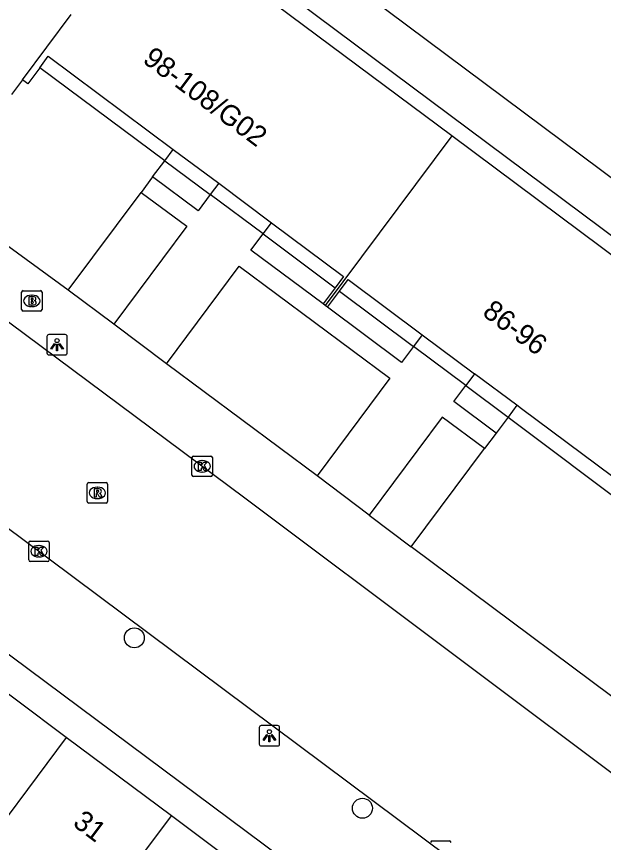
# Model space of a CAD drawing. Extents: x 160026 to 161302, y 384757 to 385701.
# Drawn here: x 160322.72 to 160351.49, y 385268.03 to 385308.52 of the extents above; entities that cross this region are included whole.
import ezdxf

# ---------------------------------------------------------------- set-up
doc = ezdxf.new("R2010")
doc.units = 0
for name, color, linetype in [('IMGEO_Boom', 7, 'Continuous'), ('IMGEO_Brandkraan', 7, 'Continuous'), ('IMGEO_Groenvoorziening', 7, 'Continuous'), ('IMGEO_Kolk', 7, 'Continuous'), ('IMGEO_Lichtpunt', 7, 'Continuous'), ('IMGEO_Pand', 7, 'Continuous'), ('IMGEO_Pand_nummerreeks', 7, 'Continuous'), ('IMGEO_Rijbaan_lokaal_gesloten', 7, 'Continuous'), ('IMGEO_Rioolput', 7, 'Continuous'), ('IMGEO_Voetpad_open', 7, 'Continuous')]:
    doc.layers.add(name, color=color, linetype=linetype)

msp = doc.modelspace()

# ---------------------------------------------------------------- linework, layer by layer
at = {"layer": 'IMGEO_Boom'}
for centre in [(160328.493, 385278.063), (160339.675, 385269.709)]:
    msp.add_circle(centre, 0.489, dxfattribs=at)
at = {"layer": 'IMGEO_Brandkraan'}
for p, q in [((160322.967, 385294.157), (160322.967, 385295.009)), ((160323.042, 385295.083), (160323.894, 385295.083)), ((160323.455, 385294.863), (160323.48, 385294.863)), ((160323.968, 385295.009), (160323.968, 385294.157)), ((160323.894, 385294.083), (160323.042, 385294.083)), ((160323.478, 385294.303), (160323.453, 385294.303))]:
    msp.add_line(p, q, dxfattribs=at)
for points in [[(160322.967, 385294.157), (160322.967, 385295.009)], [(160323.042, 385295.083), (160323.894, 385295.083)], [(160323.968, 385295.009), (160323.968, 385294.157)], [(160323.315, 385294.783), (160323.315, 385294.383), (160323.528, 385294.383)], [(160323.546, 385294.783), (160323.315, 385294.783)], [(160323.494, 385294.702), (160323.44, 385294.702), (160323.44, 385294.626)], [(160323.44, 385294.626), (160323.493, 385294.626)], [(160323.502, 385294.55), (160323.44, 385294.55), (160323.44, 385294.469)], [(160323.44, 385294.469), (160323.502, 385294.469)], [(160323.894, 385294.083), (160323.042, 385294.083)]]:
    msp.add_lwpolyline(points, dxfattribs=at)
for centre, radius, start, end in [((160323.044, 385295.007), 0.0765, 91.552, 178.448), ((160323.044, 385295.007), 0.0765, 91.552, 178.448), ((160323.892, 385295.007), 0.0765, 1.552, 88.448), ((160323.892, 385295.007), 0.0765, 1.552, 88.448), ((160323.495, 385294.664), 0.0379, 267.8285, 90.9355), ((160323.503, 385294.509), 0.0404, 269.8759, 90.5077), ((160323.55, 385294.638), 0.145, 59.4692, 91.5367), ((160323.575, 385294.685), 0.0922, 285.5137, 58.1501), ((160323.58, 385294.493), 0.105, 301.3115, 78.989), ((160323.044, 385294.159), 0.0765, 181.552, 268.448), ((160323.044, 385294.159), 0.0765, 181.552, 268.448), ((160323.534, 385294.634), 0.251, 268.6676, 293.5347), ((160323.892, 385294.159), 0.0765, 271.552, 358.448), ((160323.892, 385294.159), 0.0765, 271.552, 358.448)]:
    msp.add_arc(centre, radius, start, end, dxfattribs=at)
for centre, major_axis, ratio, start_param, end_param in [((160323.454, 385294.583), (-0.387, 0.002), 0.722429, 4.712389, 7.853982), ((160323.479, 385294.583), (-0.39, 0.002), 0.717154, 1.570796, 4.712389)]:
    msp.add_ellipse(centre, major_axis=major_axis, ratio=ratio, start_param=start_param, end_param=end_param, dxfattribs=at)
at = {"layer": 'IMGEO_Groenvoorziening'}
for points in [[(160329.983, 385301.454), (160332.215, 385299.791)], [(160334.805, 385297.862), (160338.342, 385295.227)], [(160338.543, 385295.063), (160342.176, 385292.346)], [(160344.743, 385290.426), (160346.813, 385288.878)]]:
    msp.add_lwpolyline(points, dxfattribs=at)
at = {"layer": 'IMGEO_Kolk'}
for p, q in [((160331.319, 385286.046), (160331.319, 385286.898)), ((160331.394, 385286.972), (160332.246, 385286.972)), ((160331.807, 385286.752), (160331.832, 385286.752)), ((160332.32, 385286.898), (160332.32, 385286.046)), ((160332.246, 385285.972), (160331.394, 385285.972)), ((160331.83, 385286.192), (160331.805, 385286.192)), ((160323.316, 385281.881), (160323.316, 385282.733)), ((160323.391, 385282.807), (160324.243, 385282.807)), ((160324.317, 385282.733), (160324.317, 385281.881)), ((160323.804, 385282.587), (160323.829, 385282.587)), ((160323.827, 385282.027), (160323.802, 385282.027)), ((160324.243, 385281.807), (160323.391, 385281.807)), ((160343.093, 385268.104), (160343.945, 385268.104))]:
    msp.add_line(p, q, dxfattribs=at)
for points in [[(160331.319, 385286.046), (160331.319, 385286.898)], [(160331.394, 385286.972), (160332.246, 385286.972)], [(160332.32, 385286.898), (160332.32, 385286.046)], [(160331.64, 385286.672), (160331.763, 385286.672), (160331.763, 385286.521), (160331.893, 385286.672), (160332.057, 385286.672), (160331.911, 385286.521), (160332.064, 385286.272), (160331.912, 385286.272), (160331.827, 385286.436), (160331.763, 385286.369), (160331.763, 385286.272), (160331.64, 385286.272), (160331.64, 385286.672)], [(160332.246, 385285.972), (160331.394, 385285.972)], [(160323.316, 385281.881), (160323.316, 385282.733)], [(160323.391, 385282.807), (160324.243, 385282.807)], [(160324.317, 385282.733), (160324.317, 385281.881)], [(160323.637, 385282.507), (160323.76, 385282.507), (160323.76, 385282.356), (160323.89, 385282.507), (160324.054, 385282.507), (160323.908, 385282.356), (160324.061, 385282.107), (160323.909, 385282.107), (160323.824, 385282.271), (160323.76, 385282.204), (160323.76, 385282.107), (160323.637, 385282.107), (160323.637, 385282.507)], [(160324.243, 385281.807), (160323.391, 385281.807)], [(160343.093, 385268.104), (160343.945, 385268.104)]]:
    msp.add_lwpolyline(points, dxfattribs=at)
for centre, start, end in [((160331.396, 385286.896), 91.552, 178.448), ((160331.396, 385286.896), 91.552, 178.448), ((160332.244, 385286.896), 1.552, 88.448), ((160332.244, 385286.896), 1.552, 88.448), ((160331.396, 385286.048), 181.552, 268.448), ((160331.396, 385286.048), 181.552, 268.448), ((160332.244, 385286.048), 271.552, 358.448), ((160332.244, 385286.048), 271.552, 358.448), ((160323.393, 385282.731), 91.552, 178.448), ((160323.393, 385282.731), 91.552, 178.448), ((160324.241, 385282.731), 1.552, 88.448), ((160324.241, 385282.731), 1.552, 88.448), ((160323.393, 385281.883), 181.552, 268.448), ((160323.393, 385281.883), 181.552, 268.448), ((160324.241, 385281.883), 271.552, 358.448), ((160324.241, 385281.883), 271.552, 358.448), ((160343.095, 385268.028), 91.552, 178.448), ((160343.095, 385268.028), 91.552, 178.448), ((160343.943, 385268.028), 1.552, 88.448), ((160343.943, 385268.028), 1.552, 88.448)]:
    msp.add_arc(centre, 0.0765, start, end, dxfattribs=at)
for centre, major_axis, ratio, start_param, end_param in [((160331.806, 385286.472), (-0.387, 0.002), 0.722429, 4.712389, 7.853982), ((160331.831, 385286.472), (-0.39, 0.002), 0.717154, 1.570796, 4.712389), ((160323.803, 385282.307), (-0.387, 0.002), 0.722429, 4.712389, 7.853982), ((160323.828, 385282.307), (-0.39, 0.002), 0.717154, 1.570796, 4.712389)]:
    msp.add_ellipse(centre, major_axis=major_axis, ratio=ratio, start_param=start_param, end_param=end_param, dxfattribs=at)
at = {"layer": 'IMGEO_Lichtpunt'}
for p, q in [((160324.205, 385292.837), (160324.205, 385292.03)), ((160324.205, 385292.837), (160324.205, 385292.03)), ((160325.107, 385292.932), (160324.299, 385292.932)), ((160325.107, 385292.932), (160324.299, 385292.932)), ((160325.201, 385292.03), (160325.201, 385292.837)), ((160325.201, 385292.03), (160325.201, 385292.837)), ((160324.299, 385291.936), (160325.107, 385291.936)), ((160324.299, 385291.936), (160325.107, 385291.936)), ((160334.616, 385273.663), (160334.616, 385272.856)), ((160334.616, 385273.663), (160334.616, 385272.856)), ((160335.518, 385273.758), (160334.71, 385273.758)), ((160335.518, 385273.758), (160334.71, 385273.758)), ((160335.612, 385272.856), (160335.612, 385273.663)), ((160335.612, 385272.856), (160335.612, 385273.663)), ((160334.71, 385272.762), (160335.518, 385272.762)), ((160334.71, 385272.762), (160335.518, 385272.762))]:
    msp.add_line(p, q, dxfattribs=at)
for points in [[(160324.579, 385292.501), (160324.618, 385292.473), (160324.43, 385292.211), (160324.392, 385292.238), (160324.579, 385292.501)], [(160324.681, 385292.453), (160324.728, 385292.453), (160324.728, 385292.131), (160324.681, 385292.131), (160324.681, 385292.453)], [(160324.791, 385292.473), (160324.829, 385292.5), (160325.016, 385292.238), (160324.977, 385292.21), (160324.791, 385292.473)], [(160334.99, 385273.327), (160335.029, 385273.299), (160334.841, 385273.037), (160334.803, 385273.064), (160334.99, 385273.327)], [(160335.092, 385273.279), (160335.139, 385273.279), (160335.139, 385272.957), (160335.092, 385272.957), (160335.092, 385273.279)], [(160335.202, 385273.299), (160335.24, 385273.326), (160335.427, 385273.064), (160335.388, 385273.036), (160335.202, 385273.299)]]:
    msp.add_lwpolyline(points, dxfattribs=at)
for centre in [(160324.704, 385292.635), (160335.115, 385273.461)]:
    msp.add_circle(centre, 0.0994, dxfattribs=at)
for centre, start, end in [((160324.299, 385292.837), 90, 180), ((160324.299, 385292.837), 90, 180), ((160325.107, 385292.837), 0, 90), ((160325.107, 385292.837), 0, 90), ((160324.299, 385292.03), 180, 270), ((160324.299, 385292.03), 180, 270), ((160325.107, 385292.03), 270, 0), ((160325.107, 385292.03), 270, 360), ((160334.71, 385273.663), 90, 180), ((160334.71, 385273.663), 90, 180), ((160335.518, 385273.663), 0, 90), ((160335.518, 385273.663), 0, 90), ((160334.71, 385272.856), 180, 270), ((160334.71, 385272.856), 180, 270), ((160335.518, 385272.856), 270, 0), ((160335.518, 385272.856), 270, 360)]:
    msp.add_arc(centre, 0.0946, start, end, dxfattribs=at)
at = {"layer": 'IMGEO_Pand'}
for points in [[(160344.055, 385302.669), (160329.511, 385313.511), (160329.975, 385314.134)], [(160323.007, 385305.421), (160325.396, 385308.625)], [(160323.86, 385306.015), (160324.276, 385306.573), (160330.397, 385302.01)], [(160323.86, 385306.015), (160323.271, 385305.224), (160323.007, 385305.421)], [(160344.055, 385302.669), (160337.856, 385294.359)], [(160358.796, 385291.679), (160344.055, 385302.669)], [(160330.397, 385302.01), (160332.629, 385300.346)], [(160332.629, 385300.346), (160335.219, 385298.415)], [(160335.219, 385298.415), (160338.754, 385295.78), (160338.342, 385295.227)], [(160338.543, 385295.063), (160338.969, 385295.634), (160342.606, 385292.923)], [(160338.342, 385295.227), (160337.752, 385294.436)], [(160337.96, 385294.281), (160338.543, 385295.063)], [(160337.856, 385294.359), (160337.752, 385294.436)], [(160337.96, 385294.281), (160337.856, 385294.359)], [(160342.606, 385292.923), (160345.176, 385291.006)], [(160347.248, 385289.462), (160345.176, 385291.006)], [(160352.984, 385284.263), (160353.426, 385284.856), (160347.481, 385289.288), (160347.248, 385289.462)], [(160325.158, 385273.181), (160320.269, 385276.833)], [(160325.158, 385273.181), (160320.348, 385266.743), (160319.67, 385265.835)], [(160330.307, 385269.334), (160325.158, 385273.181)], [(160325.498, 385262.895), (160330.307, 385269.334)], [(160335.568, 385265.404), (160330.307, 385269.334)]]:
    msp.add_lwpolyline(points, dxfattribs=at)
at = {"layer": 'IMGEO_Rijbaan_lokaal_gesloten'}
for points in [[(160316.228, 385298.079), (160333.903, 385284.92), (160353.887, 385269.963), (160380.549, 385250.106)], [(160311.4, 385291.54), (160323.03, 385282.896), (160343.93, 385267.299)]]:
    msp.add_lwpolyline(points, dxfattribs=at)
at = {"layer": 'IMGEO_Rioolput'}
for p, q in [((160326.18, 385284.745), (160326.18, 385285.597)), ((160326.255, 385285.671), (160327.107, 385285.671)), ((160327.181, 385285.597), (160327.181, 385284.745)), ((160326.668, 385285.451), (160326.693, 385285.451)), ((160326.691, 385284.891), (160326.666, 385284.891)), ((160327.107, 385284.671), (160326.255, 385284.671))]:
    msp.add_line(p, q, dxfattribs=at)
for points in [[(160326.18, 385284.745), (160326.18, 385285.597)], [(160326.255, 385285.671), (160327.107, 385285.671)], [(160327.181, 385285.597), (160327.181, 385284.745)], [(160326.769, 385285.369), (160326.517, 385285.371), (160326.517, 385284.971)], [(160326.517, 385284.971), (160326.641, 385284.971), (160326.641, 385285.133), (160326.652, 385285.133)], [(160326.695, 385285.29), (160326.641, 385285.29), (160326.641, 385285.209)], [(160326.641, 385285.209), (160326.693, 385285.209)], [(160326.699, 385285.104), (160326.77, 385284.971), (160326.91, 385284.971), (160326.845, 385285.097)], [(160327.107, 385284.671), (160326.255, 385284.671)]]:
    msp.add_lwpolyline(points, dxfattribs=at)
for centre, radius, start, end in [((160326.257, 385285.595), 0.0765, 91.552, 178.448), ((160326.257, 385285.595), 0.0765, 91.552, 178.448), ((160327.105, 385285.595), 0.0765, 1.552, 88.448), ((160327.105, 385285.595), 0.0765, 1.552, 88.448), ((160326.651, 385285.08), 0.0533, 26.0293, 88.6989), ((160326.677, 385285.398), 0.19, 274.7715, 282.9687), ((160326.701, 385285.194), 0.0964, 77.0061, 93.1865), ((160326.715, 385285.251), 0.0378, 276.6634, 79.6772), ((160326.768, 385285.259), 0.109, 350.3612, 89.416), ((160326.766, 385285.259), 0.112, 277.5842, 350.9817), ((160326.75, 385285.044), 0.108, 29.5134, 73.7905), ((160326.257, 385284.747), 0.0765, 181.552, 268.448), ((160326.257, 385284.747), 0.0765, 181.552, 268.448), ((160327.105, 385284.747), 0.0765, 271.552, 358.448), ((160327.105, 385284.747), 0.0765, 271.552, 358.448)]:
    msp.add_arc(centre, radius, start, end, dxfattribs=at)
for centre, major_axis, ratio, start_param, end_param in [((160326.667, 385285.171), (-0.387, 0.002), 0.722429, 4.712389, 7.853982), ((160326.692, 385285.171), (-0.39, 0.002), 0.717154, 1.570796, 4.712389)]:
    msp.add_ellipse(centre, major_axis=major_axis, ratio=ratio, start_param=start_param, end_param=end_param, dxfattribs=at)
at = {"layer": 'IMGEO_Voetpad_open'}
for points in [[(160388.692, 385270.335), (160329.975, 385314.134)], [(160394.21, 385269.049), (160339.974, 385309.507)], [(160329.983, 385301.454), (160323.86, 385306.015)], [(160323.007, 385305.421), (160322.466, 385304.695)], [(160329.983, 385301.454), (160330.397, 385302.01)], [(160329.39, 385300.658), (160329.983, 385301.454)], [(160329.39, 385300.658), (160328.828, 385299.904)], [(160332.215, 385299.791), (160331.621, 385298.995), (160329.39, 385300.658)], [(160332.629, 385300.346), (160332.215, 385299.791)], [(160325.253, 385295.108), (160318.811, 385299.794)], [(160325.253, 385295.108), (160328.828, 385299.904)], [(160328.828, 385299.904), (160331.059, 385298.241), (160327.484, 385293.444)], [(160334.805, 385297.862), (160332.215, 385299.791)], [(160334.805, 385297.862), (160335.219, 385298.415)], [(160337.752, 385294.436), (160334.21, 385297.066), (160334.805, 385297.862)], [(160330.067, 385291.504), (160333.636, 385296.292), (160341.017, 385290.79), (160337.448, 385286.002)], [(160327.484, 385293.444), (160325.253, 385295.108)], [(160342.176, 385292.346), (160341.593, 385291.563), (160337.96, 385294.281)], [(160330.067, 385291.504), (160327.484, 385293.444)], [(160342.606, 385292.923), (160342.176, 385292.346)], [(160344.743, 385290.426), (160342.176, 385292.346)], [(160337.448, 385286.002), (160330.067, 385291.504)], [(160345.176, 385291.006), (160344.743, 385290.426)], [(160346.234, 385288.103), (160344.162, 385289.647), (160344.743, 385290.426)], [(160306.008, 385289.412), (160336.475, 385266.714)], [(160347.248, 385289.462), (160346.813, 385288.878)], [(160345.662, 385287.338), (160343.592, 385288.882), (160340.004, 385284.069)], [(160346.813, 385288.878), (160346.234, 385288.103)], [(160346.813, 385288.878), (160352.984, 385284.263)], [(160346.234, 385288.103), (160345.662, 385287.338)], [(160342.067, 385282.531), (160345.662, 385287.338)], [(160340.004, 385284.069), (160337.448, 385286.002)], [(160340.004, 385284.069), (160342.067, 385282.531)], [(160354.867, 385272.988), (160342.067, 385282.531)]]:
    msp.add_lwpolyline(points, dxfattribs=at)

# ---------------------------------------------------------------- texts
at = {"layer": 'IMGEO_Pand_nummerreeks'}
for s, rotation, p in [('98-108/G02', 323.2964, (160328.85, 385306.307)), ('86-96', 323.2963, (160345.502, 385293.907)), ('31', 323.239, (160325.424, 385268.887))]:
    msp.add_text(s, height=1, rotation=rotation, dxfattribs=at).set_placement(p)

doc.saveas('drawing.dxf')
